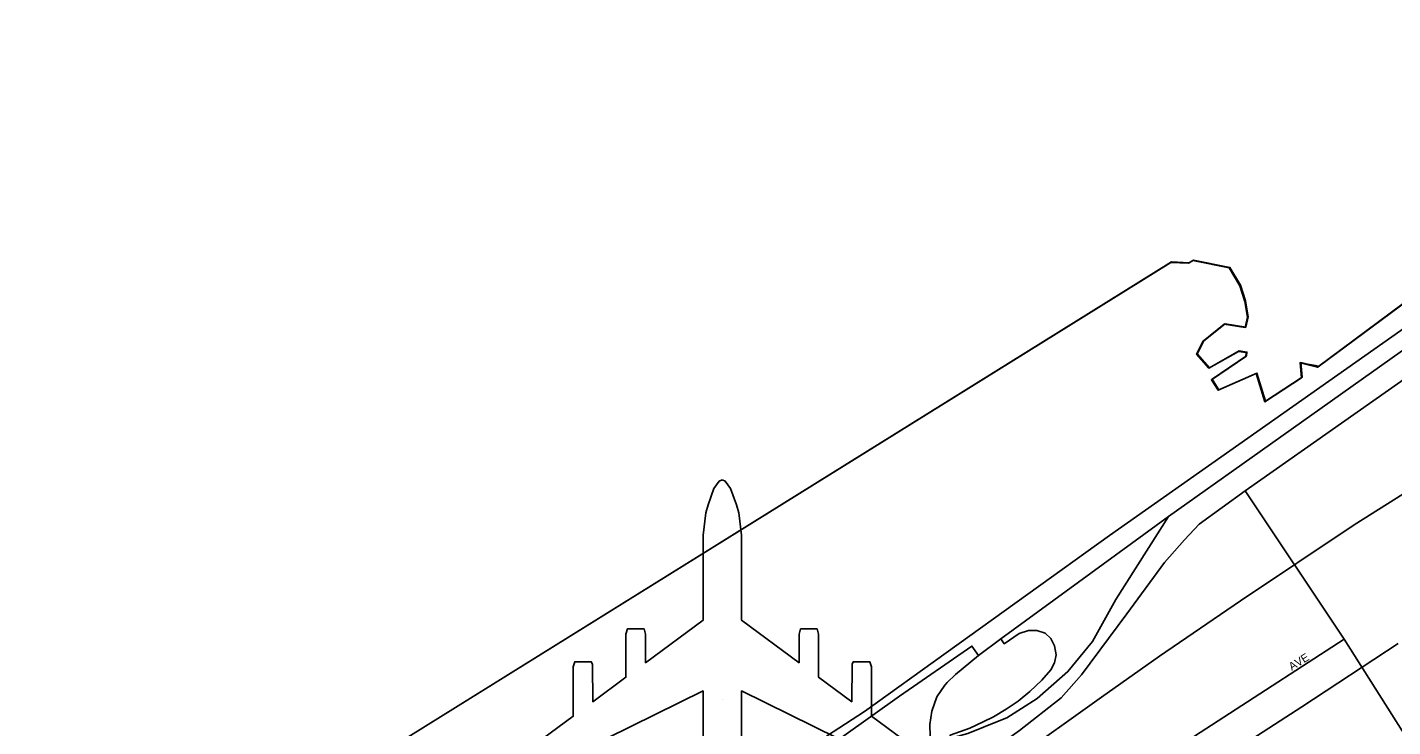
# Model space of a CAD drawing. Extents: x 2139079 to 2262683, y 1235796 to 1334992.
# Drawn here: x 2188799 to 2197328, y 1282370 to 1286738 of the extents above; entities that cross this region are included whole.
import ezdxf

# ---------------------------------------------------------------- set-up
doc = ezdxf.new("R2010")
doc.units = 0
for name, color, linetype in [('GM_X_Airport_Class_1', 7, 'Continuous'), ('GM_X_Airport_Location_Class_1', 7, 'Continuous'), ('GM_X_City_Street', 7, 'Continuous'), ('GM_X_City_Street_Text', 7, 'Continuous'), ('GM_X_Interchange_Ramps', 7, 'Continuous'), ('GM_X_Interstate_Route', 7, 'Continuous'), ('GM_X_Major_Lake', 7, 'Continuous'), ('GM_X_Major_River', 7, 'Continuous'), ('GM_X_Rail_Line', 7, 'Continuous'), ('GM_X_State_Route', 7, 'Continuous')]:
    doc.layers.add(name, color=color, linetype=linetype)

msp = doc.modelspace()

# ---------------------------------------------------------------- linework, layer by layer
at = {"layer": 'GM_X_Airport_Class_1'}
for points in [[(2191673.7, 1282039.4), (2192209.1, 1282435.3), (2192209.1, 1282743.1), (2192218.6, 1282775.8), (2192322.2, 1282775.8), (2192329.4, 1282759.4), (2192331.6, 1282525.9), (2192538.4, 1282678.8), (2192538.4, 1282947.4), (2192547.9, 1282980.1), (2192651.5, 1282980.1), (2192660.9, 1282947.4), (2192660.9, 1282769.4), (2193020, 1283034.9), (2193020, 1283565.4), (2193037.5, 1283705.7), (2193052.1, 1283755.7), (2193088.1, 1283857.8), (2193121.3, 1283903.2), (2193140.2, 1283911.2)], [(2193140.2, 1283911.2), (2193159.2, 1283903.2), (2193192.4, 1283857.8), (2193228.4, 1283755.7), (2193243, 1283705.7), (2193260.5, 1283565.4), (2193260.5, 1283034.9), (2193619.6, 1282769.4), (2193619.6, 1282947.4), (2193629, 1282980.1), (2193732.6, 1282980.1), (2193742.1, 1282947.4), (2193742.1, 1282678.8), (2193948.9, 1282525.9), (2193951.1, 1282759.4), (2193958.3, 1282775.8), (2194061.9, 1282775.8), (2194071.4, 1282743.1), (2194071.4, 1282435.3), (2194606.8, 1282039.4)], [(2193020, 1282263.2), (2193020, 1282593.4), (2191673.7, 1281929.9)], [(2194606.8, 1281929.9), (2193260.5, 1282593.4), (2193260.5, 1282263.2)]]:
    msp.add_lwpolyline(points, dxfattribs=at)
at = {"layer": 'GM_X_Airport_Location_Class_1'}
msp.add_line((2193140.2, 1282539.4), (2193140.2, 1282539.4), dxfattribs=at)
at = {"layer": 'GM_X_City_Street'}
for points in [[(2198073.7, 1285333.4), (2195559.4, 1283563), (2194028, 1282464.6), (2193791.3, 1282310.1)], [(2193289.3, 1281359), (2193299.7, 1281367.3), (2193552, 1281546.9), (2193802.9, 1281728.2), (2193935.7, 1281815.7), (2194084.6, 1281878.9), (2194378.3, 1281974.7), (2194463.9, 1282006.1), (2194512.4, 1282028.8), (2194561, 1282051.6), (2194694.7, 1282130.5), (2194996.1, 1282346.7), (2195257.9, 1282550.9), (2195383.5, 1282693.6), (2195668, 1283075.6), (2195903.1, 1283394.7), (2196027, 1283536.1), (2196119.5, 1283633.9), (2196406.7, 1283843.3), (2197904.1, 1284893.8)], [(2199693.1, 1274636.1), (2199757.3, 1274882.4), (2199487.9, 1276121.4), (2199423.7, 1276514.9), (2199347, 1276984.3), (2199266.6, 1277477.3), (2199158.9, 1278137), (2199026, 1278950.7), (2198913.3, 1279950.5), (2198889.4, 1280010.3), (2198105.6, 1281211.1), (2197516.4, 1282140.7), (2197025, 1282915.9), (2196406.7, 1283843.3)], [(2194295.9, 1280994.8), (2194592.7, 1281234.1), (2194909, 1281470.8), (2195521.2, 1281942), (2197025, 1282915.9)]]:
    msp.add_lwpolyline(points, dxfattribs=at)
at = {"layer": 'GM_X_Interchange_Ramps'}
for points in [[(2194880.4, 1282918), (2194901.7, 1282887.9), (2194995, 1282951.9), (2195052.2, 1282970), (2195105.3, 1282971.6), (2195158.2, 1282953.7), (2195192.3, 1282921), (2195215.9, 1282875.3), (2195225.1, 1282819.7), (2195215.6, 1282768.7), (2195193.7, 1282724.6), (2195137.1, 1282660.6), (2195062, 1282589.7), (2194987.6, 1282529), (2194913.2, 1282479.7), (2194834.2, 1282431.3), (2194771, 1282399.5), (2194685.7, 1282360.3), (2194562.9, 1282316.6), (2194568.1, 1282297.4)], [(2194741.1, 1282815.3), (2194699.3, 1282873.7), (2194248.3, 1282561.3), (2193898.6, 1282312.3), (2193475.2, 1282009.3), (2193277, 1281863.5), (2193144.2, 1281765.9), (2193164.5, 1281733.7)]]:
    msp.add_lwpolyline(points, dxfattribs=at)
at = {"layer": 'GM_X_Interstate_Route'}
for points in [[(2196450.5, 1284054), (2199934.5, 1286525.1), (2200234.4, 1286737.7)], [(2189760.3, 1281423.6), (2195942.9, 1285269.6), (2196053.2, 1285264.5), (2196079.5, 1285281.6), (2196306.8, 1285235.3), (2196372.8, 1285123.8), (2196404.4, 1285025.9), (2196422, 1284927.8), (2196407, 1284863.3), (2196276.3, 1284883.4), (2196143.5, 1284777), (2196102.7, 1284696.1), (2196180.3, 1284608.9), (2196365.2, 1284714.1), (2196413.5, 1284706.8), (2196409.9, 1284682.6), (2196195.5, 1284536.8), (2196238.7, 1284471.2), (2196475.8, 1284575.2), (2196528.7, 1284399.3), (2196759, 1284549.4), (2196749.6, 1284641.6), (2196858.3, 1284615.1), (2197540.4, 1285121.4)], [(2195927.9, 1283683.3), (2196450.5, 1284054)], [(2194545.9, 1282646.1), (2194596.4, 1282695.4), (2194741.1, 1282815.3), (2194880.4, 1282918), (2195927.9, 1283683.3)], [(2194451.2, 1282262), (2194450.3, 1282265.4), (2194439.2, 1282308), (2194437.7, 1282382.7), (2194448.6, 1282466.7), (2194479.7, 1282555.4), (2194529.5, 1282630.1), (2194545.9, 1282646.1)]]:
    msp.add_lwpolyline(points, dxfattribs=at)
at = {"layer": 'GM_X_Major_Lake'}
for points in [[(2189764.7, 1281426.2), (2195947.3, 1285272.1), (2196057.6, 1285267), (2196083.9, 1285284.2)], [(2196083.9, 1285284.2), (2196311.2, 1285237.9), (2196377.2, 1285126.4), (2196408.8, 1285028.5), (2196426.4, 1284930.4), (2196411.4, 1284865.9), (2196280.7, 1284886), (2196147.9, 1284779.6), (2196107.1, 1284698.6), (2196184.7, 1284611.5), (2196369.6, 1284716.7), (2196417.9, 1284709.4), (2196414.3, 1284685.2), (2196199.9, 1284539.4), (2196243.1, 1284473.8), (2196480.2, 1284577.8), (2196533.1, 1284401.9), (2196763.4, 1284551.9), (2196753.9, 1284644.2), (2196862.7, 1284617.7), (2197544.8, 1285124)], [(2196083.9, 1285284.2), (2196311.2, 1285237.9), (2196377.2, 1285126.4), (2196408.8, 1285028.5), (2196426.4, 1284930.4), (2196411.4, 1284865.9), (2196280.7, 1284886), (2196147.9, 1284779.6), (2196107.1, 1284698.6), (2196184.7, 1284611.5), (2196369.6, 1284716.7), (2196417.9, 1284709.4), (2196414.3, 1284685.2), (2196199.9, 1284539.4), (2196243.1, 1284473.8), (2196480.2, 1284577.8), (2196533.1, 1284401.9), (2196763.4, 1284551.9), (2196753.9, 1284644.2), (2196862.7, 1284617.7), (2197544.8, 1285124)], [(2196083.9, 1285284.2), (2196311.2, 1285237.9), (2196377.2, 1285126.4), (2196408.8, 1285028.5), (2196426.4, 1284930.4), (2196411.4, 1284865.9), (2196280.7, 1284886), (2196147.9, 1284779.6), (2196107.1, 1284698.6), (2196184.7, 1284611.5), (2196369.6, 1284716.7), (2196417.9, 1284709.4), (2196414.3, 1284685.2), (2196199.9, 1284539.4), (2196243.1, 1284473.8), (2196480.2, 1284577.8), (2196533.1, 1284401.9), (2196763.4, 1284551.9), (2196753.9, 1284644.2), (2196862.7, 1284617.7), (2197544.8, 1285124)]]:
    msp.add_lwpolyline(points, dxfattribs=at)
at = {"layer": 'GM_X_Major_River'}
msp.add_line((2196746.2, 1284641.8), (2196858.2, 1284623.6), dxfattribs=at)
at = {"layer": 'GM_X_Rail_Line'}
for points in [[(2188798.9, 1277974.5), (2189752.1, 1278588.8), (2190639.6, 1279116), (2192678, 1280555.1), (2194231.5, 1281639.3), (2194948.6, 1282154.6), (2195509, 1282554.5), (2195871.7, 1282810.1), (2196378.5, 1283156.3), (2197087.3, 1283630.4), (2199383.9, 1285076.5), (2199860.7, 1285394.8)], [(2194416.4, 1280986.7), (2194514.1, 1281040.4), (2194576, 1281078.4), (2194641.6, 1281120.9), (2194698.3, 1281162.7), (2194762.5, 1281209.7), (2194832.6, 1281260.4), (2194887, 1281299.9), (2194925.8, 1281323.8), (2195019.7, 1281384.9), (2195316.5, 1281578.8), (2195387.4, 1281616.8), (2195453.7, 1281648.9), (2195636.5, 1281764.5), (2196384.2, 1282250.1), (2196761.5, 1282494.8), (2197362, 1282889.7)]]:
    msp.add_lwpolyline(points, dxfattribs=at)
at = {"layer": 'GM_X_State_Route'}
for points in [[(2195010.3, 1282483.7), (2195106.5, 1282545), (2195299.4, 1282714.4), (2195452.3, 1282902.7), (2195598.2, 1283163.9), (2195927.9, 1283683.3)], [(2194870.4, 1282405.6), (2194918.3, 1282425), (2195010.3, 1282483.7)], [(2194152, 1282190.5), (2194398.8, 1282251.4), (2194450.3, 1282265.4), (2194568.1, 1282297.4), (2194675.2, 1282326.5), (2194870.4, 1282405.6)]]:
    msp.add_lwpolyline(points, dxfattribs=at)

# ---------------------------------------------------------------- texts
at = {"layer": 'GM_X_City_Street_Text'}
msp.add_text('AVE', height=50, rotation=32.01275, dxfattribs=at).set_placement((2196698, 1282719))

doc.saveas('drawing.dxf')
